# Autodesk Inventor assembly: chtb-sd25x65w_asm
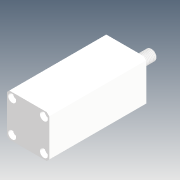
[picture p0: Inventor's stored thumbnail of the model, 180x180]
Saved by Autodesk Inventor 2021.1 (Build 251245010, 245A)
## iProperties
Company: Microsoft
Created: 2018-05
Part Number: chtb-sd25x65w_asm
Description: STEP AP214
Document SubType Name: Assembly
Designer: user
Title: chtb-sd25x65w_asm.STEP
Author: Windows
Revision Number: ÈÎºÎ
Sending System: SolidWorks 2015
Preprocessor: SwSTEP 2.0
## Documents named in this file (4)
- D:\Vault_2016\Projekty\Clamptek\Hydraulic\CHTB\CHTB-25\Inventor\chtb-sd25x65w\chtb-sd25x65w_asm.iam
- D:\Vault_2016\Projekty\Clamptek\Hydraulic\CHTB\CHTB-25\Inventor\chtb-sd25x65w\CHTB-25QG.ipt
- D:\Vault_2016\Projekty\Clamptek\Hydraulic\CHTB\CHTB-25\Inventor\chtb-sd25x65w\CHTB-SD25X65NBT.ipt
- D:\Vault_2016\Projekty\Clamptek\Hydraulic\CHTB\CHTB-25\Inventor\chtb-sd25x65w\CHTB-SD25X65WHSG.ipt
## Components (3 placed, 3 different names)
1. CHTB-25QG_1
2. CHTB-SD25X65NBT_2
3. CHTB-SD25X65WHSG_3
